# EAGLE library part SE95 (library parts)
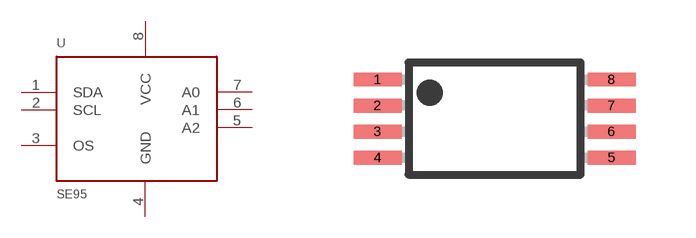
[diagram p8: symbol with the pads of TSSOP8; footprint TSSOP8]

Designator prefix -

## SE95  [TSSOP8]
1  SDA
2  SCL
3  OS
4  GND
5  A2
6  A1
7  A0
8  VCC

## Footprint TSSOP8 (pad centres in mm)
Plastic Small Outline
smd 1.2 x 0.35: 1 -2.925,0.975; 2 -2.925,0.325; 3 -2.925,-0.325; 4 -2.925,-0.975; 5 2.925,-0.975; 6 2.925,-0.325; 7 2.925,0.325; 8 2.925,0.975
